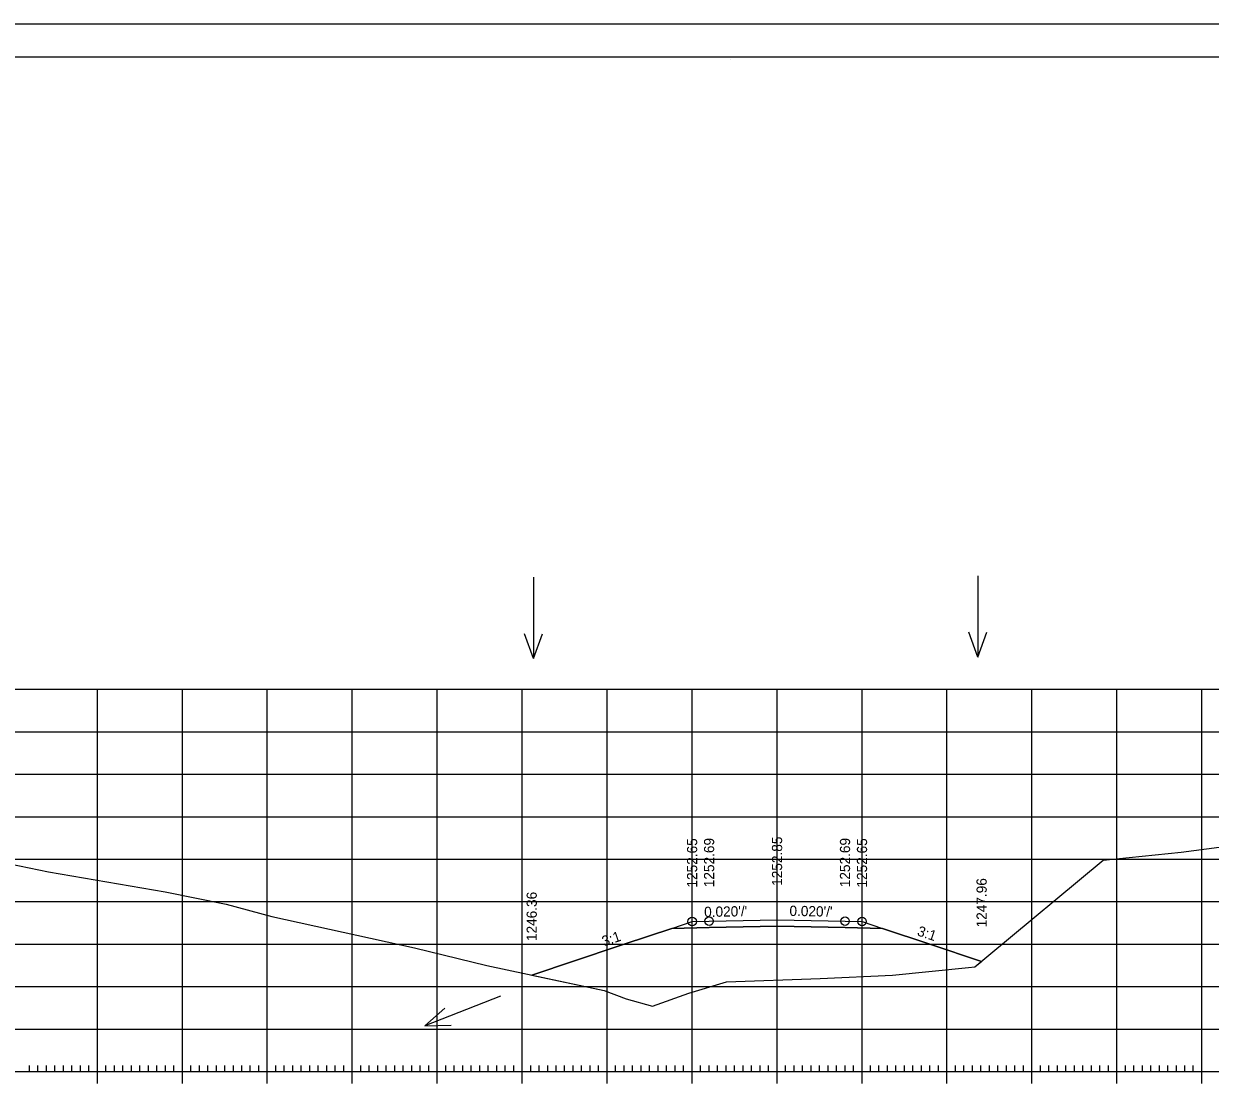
# Model space of a CAD drawing. Extents: x 1406028 to 1412453, y 321733 to 325986.
# Drawn here: x 1408966.1 to 1409105.8, y 322357.5 to 322482.9 of the extents above; entities that cross this region are included whole.
import ezdxf

# ---------------------------------------------------------------- set-up
doc = ezdxf.new("R2010")
doc.units = 0
for name, color, linetype in [('R_Alt Surface', 7, 'Continuous'), ('R_Axis', 7, 'Continuous'), ('R_Border', 7, 'Continuous'), ('R_Exist Surface', 7, 'Continuous'), ('R_Fin Surface', 7, 'Continuous'), ('R_Fin Surface Annot', 7, 'Continuous'), ('R_Grid', 7, 'Continuous'), ('R_No Plot', 7, 'Continuous'), ('R_Water Annot', 7, 'Continuous')]:
    doc.layers.add(name, color=color, linetype=linetype)

msp = doc.modelspace()

# ---------------------------------------------------------------- linework, layer by layer
at = {"layer": 'R_Alt Surface'}
msp.add_lwpolyline([(1409042.42, 322376.41), (1409046.81, 322376.5), (1409054.81, 322376.66), (1409062.81, 322376.5), (1409067.21, 322376.41)], dxfattribs=at)
at = {"layer": 'R_Axis'}
for p, q in [((1408966.81, 322359.55), (1408966.81, 322360.25)), ((1408967.81, 322359.55), (1408967.81, 322360.25)), ((1408968.81, 322359.55), (1408968.81, 322360.25)), ((1408969.81, 322359.55), (1408969.81, 322360.25)), ((1408970.81, 322359.55), (1408970.81, 322360.25)), ((1408971.81, 322359.55), (1408971.81, 322360.25)), ((1408972.81, 322359.55), (1408972.81, 322360.25)), ((1408973.81, 322359.55), (1408973.81, 322360.25)), ((1408974.81, 322358.15), (1408974.81, 322360.95)), ((1408975.81, 322359.55), (1408975.81, 322360.25)), ((1408976.81, 322359.55), (1408976.81, 322360.25)), ((1408977.81, 322359.55), (1408977.81, 322360.25)), ((1408978.81, 322359.55), (1408978.81, 322360.25)), ((1408979.81, 322359.55), (1408979.81, 322360.25)), ((1408980.81, 322359.55), (1408980.81, 322360.25)), ((1408981.81, 322359.55), (1408981.81, 322360.25)), ((1408982.81, 322359.55), (1408982.81, 322360.25)), ((1408983.81, 322359.55), (1408983.81, 322360.25)), ((1408984.81, 322358.15), (1408984.81, 322360.95)), ((1408985.81, 322359.55), (1408985.81, 322360.25)), ((1408986.81, 322359.55), (1408986.81, 322360.25)), ((1408987.81, 322359.55), (1408987.81, 322360.25)), ((1408988.81, 322359.55), (1408988.81, 322360.25)), ((1408989.81, 322359.55), (1408989.81, 322360.25)), ((1408990.81, 322359.55), (1408990.81, 322360.25)), ((1408991.81, 322359.55), (1408991.81, 322360.25)), ((1408992.81, 322359.55), (1408992.81, 322360.25)), ((1408993.81, 322359.55), (1408993.81, 322360.25)), ((1408994.81, 322358.15), (1408994.81, 322360.95)), ((1408995.81, 322359.55), (1408995.81, 322360.25)), ((1408996.81, 322359.55), (1408996.81, 322360.25)), ((1408997.81, 322359.55), (1408997.81, 322360.25)), ((1408998.81, 322359.55), (1408998.81, 322360.25)), ((1408999.81, 322359.55), (1408999.81, 322360.25)), ((1409000.81, 322359.55), (1409000.81, 322360.25)), ((1409001.81, 322359.55), (1409001.81, 322360.25)), ((1409002.81, 322359.55), (1409002.81, 322360.25)), ((1409003.81, 322359.55), (1409003.81, 322360.25)), ((1409004.81, 322358.15), (1409004.81, 322360.95)), ((1409005.81, 322359.55), (1409005.81, 322360.25)), ((1409006.81, 322359.55), (1409006.81, 322360.25)), ((1409007.81, 322359.55), (1409007.81, 322360.25)), ((1409008.81, 322359.55), (1409008.81, 322360.25)), ((1409009.81, 322359.55), (1409009.81, 322360.25)), ((1409010.81, 322359.55), (1409010.81, 322360.25)), ((1409011.81, 322359.55), (1409011.81, 322360.25)), ((1409012.81, 322359.55), (1409012.81, 322360.25)), ((1409013.81, 322359.55), (1409013.81, 322360.25)), ((1409014.81, 322358.15), (1409014.81, 322360.95)), ((1409015.81, 322359.55), (1409015.81, 322360.25)), ((1409016.81, 322359.55), (1409016.81, 322360.25)), ((1409017.81, 322359.55), (1409017.81, 322360.25)), ((1409018.81, 322359.55), (1409018.81, 322360.25)), ((1409019.81, 322359.55), (1409019.81, 322360.25)), ((1409020.81, 322359.55), (1409020.81, 322360.25)), ((1409021.81, 322359.55), (1409021.81, 322360.25)), ((1409022.81, 322359.55), (1409022.81, 322360.25)), ((1409023.81, 322359.55), (1409023.81, 322360.25)), ((1409024.81, 322358.15), (1409024.81, 322360.95)), ((1409025.81, 322359.55), (1409025.81, 322360.25)), ((1409026.81, 322359.55), (1409026.81, 322360.25)), ((1409027.81, 322359.55), (1409027.81, 322360.25)), ((1409028.81, 322359.55), (1409028.81, 322360.25)), ((1409029.81, 322359.55), (1409029.81, 322360.25)), ((1409030.81, 322359.55), (1409030.81, 322360.25)), ((1409031.81, 322359.55), (1409031.81, 322360.25)), ((1409032.81, 322359.55), (1409032.81, 322360.25)), ((1409033.81, 322359.55), (1409033.81, 322360.25)), ((1409034.81, 322358.15), (1409034.81, 322360.95)), ((1409035.81, 322359.55), (1409035.81, 322360.25)), ((1409036.81, 322359.55), (1409036.81, 322360.25)), ((1409037.81, 322359.55), (1409037.81, 322360.25)), ((1409038.81, 322359.55), (1409038.81, 322360.25)), ((1409039.81, 322359.55), (1409039.81, 322360.25)), ((1409040.81, 322359.55), (1409040.81, 322360.25)), ((1409041.81, 322359.55), (1409041.81, 322360.25)), ((1409042.81, 322359.55), (1409042.81, 322360.25)), ((1409043.81, 322359.55), (1409043.81, 322360.25)), ((1409044.81, 322358.15), (1409044.81, 322360.95)), ((1409045.81, 322359.55), (1409045.81, 322360.25)), ((1409046.81, 322359.55), (1409046.81, 322360.25)), ((1409047.81, 322359.55), (1409047.81, 322360.25)), ((1409048.81, 322359.55), (1409048.81, 322360.25)), ((1409049.81, 322359.55), (1409049.81, 322360.25)), ((1409050.81, 322359.55), (1409050.81, 322360.25)), ((1409051.81, 322359.55), (1409051.81, 322360.25)), ((1409052.81, 322359.55), (1409052.81, 322360.25)), ((1409053.81, 322359.55), (1409053.81, 322360.25)), ((1409054.81, 322358.15), (1409054.81, 322360.95)), ((1409055.81, 322359.55), (1409055.81, 322360.25)), ((1409056.81, 322359.55), (1409056.81, 322360.25)), ((1409057.81, 322359.55), (1409057.81, 322360.25)), ((1409058.81, 322359.55), (1409058.81, 322360.25)), ((1409059.81, 322359.55), (1409059.81, 322360.25)), ((1409060.81, 322359.55), (1409060.81, 322360.25)), ((1409061.81, 322359.55), (1409061.81, 322360.25)), ((1409062.81, 322359.55), (1409062.81, 322360.25)), ((1409063.81, 322359.55), (1409063.81, 322360.25)), ((1409064.81, 322358.15), (1409064.81, 322360.95)), ((1409065.81, 322359.55), (1409065.81, 322360.25)), ((1409066.81, 322359.55), (1409066.81, 322360.25)), ((1409067.81, 322359.55), (1409067.81, 322360.25)), ((1409068.81, 322359.55), (1409068.81, 322360.25)), ((1409069.81, 322359.55), (1409069.81, 322360.25)), ((1409070.81, 322359.55), (1409070.81, 322360.25)), ((1409071.81, 322359.55), (1409071.81, 322360.25)), ((1409072.81, 322359.55), (1409072.81, 322360.25)), ((1409073.81, 322359.55), (1409073.81, 322360.25)), ((1409074.81, 322358.15), (1409074.81, 322360.95)), ((1409075.81, 322359.55), (1409075.81, 322360.25)), ((1409076.81, 322359.55), (1409076.81, 322360.25)), ((1409077.81, 322359.55), (1409077.81, 322360.25)), ((1409078.81, 322359.55), (1409078.81, 322360.25)), ((1409079.81, 322359.55), (1409079.81, 322360.25)), ((1409080.81, 322359.55), (1409080.81, 322360.25)), ((1409081.81, 322359.55), (1409081.81, 322360.25)), ((1409082.81, 322359.55), (1409082.81, 322360.25)), ((1409083.81, 322359.55), (1409083.81, 322360.25)), ((1409084.81, 322358.15), (1409084.81, 322360.95)), ((1409085.81, 322359.55), (1409085.81, 322360.25)), ((1409086.81, 322359.55), (1409086.81, 322360.25)), ((1409087.81, 322359.55), (1409087.81, 322360.25)), ((1409088.81, 322359.55), (1409088.81, 322360.25)), ((1409089.81, 322359.55), (1409089.81, 322360.25)), ((1409090.81, 322359.55), (1409090.81, 322360.25)), ((1409091.81, 322359.55), (1409091.81, 322360.25)), ((1409092.81, 322359.55), (1409092.81, 322360.25)), ((1409093.81, 322359.55), (1409093.81, 322360.25)), ((1409094.81, 322358.15), (1409094.81, 322360.95)), ((1409095.81, 322359.55), (1409095.81, 322360.25)), ((1409096.81, 322359.55), (1409096.81, 322360.25)), ((1409097.81, 322359.55), (1409097.81, 322360.25)), ((1409098.81, 322359.55), (1409098.81, 322360.25)), ((1409099.81, 322359.55), (1409099.81, 322360.25)), ((1409100.81, 322359.55), (1409100.81, 322360.25)), ((1409101.81, 322359.55), (1409101.81, 322360.25)), ((1409102.81, 322359.55), (1409102.81, 322360.25)), ((1409103.81, 322359.55), (1409103.81, 322360.25)), ((1409104.81, 322358.15), (1409104.81, 322360.95)), ((1408914.81, 322359.55), (1409194.81, 322359.55))]:
    msp.add_line(p, q, dxfattribs=at)
at = {"layer": 'R_Border'}
for p, q in [((1408896.81, 322479.01), (1409212.99, 322479.01)), ((1409049.33, 322478.75), (1409049.33, 322478.75)), ((1409049.33, 322478.75), (1409049.33, 322478.75))]:
    msp.add_line(p, q, dxfattribs=at)
at = {"layer": 'R_Exist Surface'}
msp.add_lwpolyline([(1408955.37, 322385.9), (1408969.05, 322383.08), (1408982.79, 322380.69), (1408989.95, 322379.27), (1408995.36, 322377.81), (1409012.15, 322374.13), (1409020.63, 322372.04), (1409034.45, 322369.09), (1409037.04, 322368.11), (1409040.15, 322367.24), (1409044.41, 322368.79), (1409048.86, 322370.13), (1409059.87, 322370.51), (1409068.41, 322370.91), (1409077.33, 322371.78), (1409078.11, 322371.86), (1409079.52, 322373.05), (1409093.18, 322384.44), (1409102.38, 322385.37), (1409106.87, 322385.98)], dxfattribs=at)
at = {"layer": 'R_Fin Surface'}
msp.add_lwpolyline([(1409025.93, 322370.91), (1409036.09, 322374.3), (1409036.81, 322374.54), (1409042.42, 322376.41), (1409044.81, 322377.21), (1409046.81, 322377.25), (1409054.81, 322377.41), (1409062.81, 322377.25), (1409064.81, 322377.21), (1409067.21, 322376.41), (1409072.81, 322374.54), (1409078.89, 322372.52)], dxfattribs=at)
at = {"layer": 'R_Grid'}
for p, q in [((1408914.81, 322404.55), (1409194.81, 322404.55)), ((1408974.81, 322359.55), (1408974.81, 322404.55)), ((1408984.81, 322359.55), (1408984.81, 322404.55)), ((1408994.81, 322359.55), (1408994.81, 322404.55)), ((1409004.81, 322359.55), (1409004.81, 322404.55)), ((1409014.81, 322359.55), (1409014.81, 322404.55)), ((1409024.81, 322359.55), (1409024.81, 322404.55)), ((1409034.81, 322359.55), (1409034.81, 322404.55)), ((1409044.81, 322359.55), (1409044.81, 322404.55)), ((1409054.81, 322359.55), (1409054.81, 322404.55)), ((1409064.81, 322359.55), (1409064.81, 322404.55)), ((1409074.81, 322359.55), (1409074.81, 322404.55)), ((1409084.81, 322359.55), (1409084.81, 322404.55)), ((1409094.81, 322359.55), (1409094.81, 322404.55)), ((1409104.81, 322359.55), (1409104.81, 322404.55)), ((1408914.81, 322399.55), (1409194.81, 322399.55)), ((1408914.81, 322394.55), (1409194.81, 322394.55)), ((1408914.81, 322389.55), (1409194.81, 322389.55)), ((1408914.81, 322384.55), (1409194.81, 322384.55)), ((1408914.81, 322379.55), (1409194.81, 322379.55)), ((1408914.81, 322374.55), (1409194.81, 322374.55)), ((1408914.81, 322369.55), (1409194.81, 322369.55)), ((1408914.81, 322364.55), (1409194.81, 322364.55)), ((1408914.81, 322359.55), (1409194.81, 322359.55))]:
    msp.add_line(p, q, dxfattribs=at)
at = {"layer": 'R_No Plot'}
msp.add_line((1408884.41, 322482.91), (1409217.75, 322482.91), dxfattribs=at)
for points in [[(1408884.41, 322482.91), (1409217.75, 322482.91), (1409217.75, 322269.57), (1408884.41, 322269.57)], [(1409130.73, 322479.01), (1409150.35, 322479.01), (1409150.35, 322469.13), (1409166.47, 322469.13), (1409189.67, 322469.13), (1409189.67, 322444.8), (1409212.99, 322444.8), (1409212.99, 322273.55), (1408896.81, 322273.55), (1408896.81, 322479.01)], [(1409025.93, 322370.91), (1409034.45, 322369.09), (1409037.04, 322368.11), (1409040.15, 322367.24), (1409044.41, 322368.79), (1409048.86, 322370.13), (1409059.87, 322370.51), (1409068.41, 322370.91), (1409077.33, 322371.78), (1409078.11, 322371.86), (1409078.89, 322372.52), (1409072.81, 322374.54), (1409067.21, 322376.41), (1409062.81, 322376.5), (1409054.81, 322376.66), (1409046.81, 322376.5), (1409042.42, 322376.41), (1409036.81, 322374.54), (1409036.09, 322374.3)]]:
    msp.add_lwpolyline(points, close=True, dxfattribs=at)
for centre in [(1409044.81, 322377.21), (1409046.81, 322377.25), (1409062.81, 322377.25), (1409064.81, 322377.21)]:
    msp.add_circle(centre, 0.5, dxfattribs=at)
at = {"layer": 'R_Water Annot'}
for p, q in [((1409026.15, 322417.74), (1409026.15, 322408.17)), ((1409078.45, 322417.9), (1409078.45, 322408.33)), ((1409026.15, 322408.17), (1409025.08, 322411.1)), ((1409026.15, 322408.17), (1409027.22, 322411.1)), ((1409078.45, 322408.33), (1409077.39, 322411.26)), ((1409078.45, 322408.33), (1409079.52, 322411.26)), ((1409022.26, 322368.43), (1409013.35, 322364.94)), ((1409013.35, 322364.94), (1409015.69, 322367)), ((1409013.35, 322364.94), (1409016.46, 322365.01))]:
    msp.add_line(p, q, dxfattribs=at)

# ---------------------------------------------------------------- texts
at = {"layer": 'R_Fin Surface Annot'}
for s, rotation, p in [('1252.65', 90, (1409045.41, 322381.21)), ('1252.69', 90, (1409047.41, 322381.25)), ('1252.85', 90, (1409055.41, 322381.41)), ('1252.69', 90, (1409063.41, 322381.25)), ('1252.65', 90, (1409065.41, 322381.21)), ('1247.96', 90, (1409079.49, 322376.52)), ('1246.36', 90, (1409026.53, 322374.91)), ("0.020'/'", 1.1458, (1409046.24, 322377.74)), ("0.020'/'", 358.8542, (1409056.26, 322377.88)), ('3:1', 18.4349, (1409034.42, 322374.27)), ('3:1', 341.5651, (1409071.22, 322375.6))]:
    msp.add_text(s, height=1.2, rotation=rotation, dxfattribs=at).set_placement(p)

doc.saveas('drawing.dxf')
